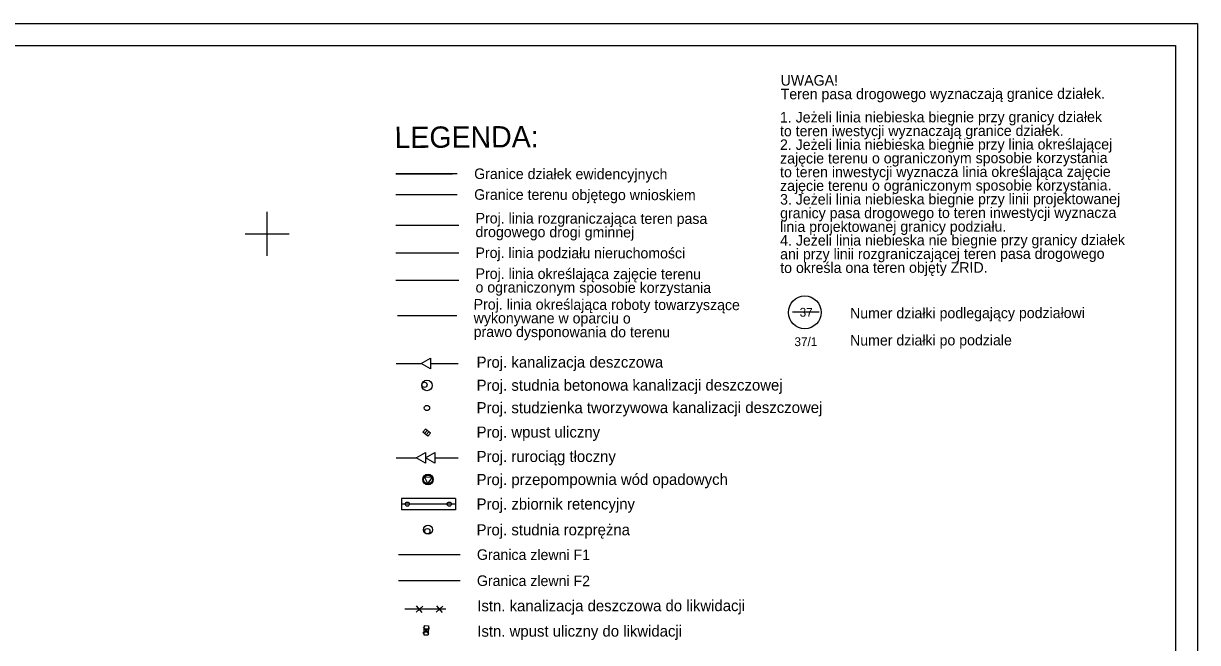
# Model space of a CAD drawing. Extents: x 6512606 to 6513006, y 6022524 to 6022728.
# Drawn here: x 6512872.3 to 6513005.7, y 6022653.6 to 6022723.9 of the extents above; entities that cross this region are included whole.
import ezdxf

# ---------------------------------------------------------------- set-up
doc = ezdxf.new("R2010")
doc.units = 0
for name, color, linetype in [('10', 7, 'Continuous'), ('211-numer działki ewidencyjnej', 7, 'Continuous'), ('3', 7, 'Continuous'), ('4', 7, 'Continuous'), ('6', 7, 'Continuous'), ('Default', 7, 'Continuous'), ('kratka ściekowa (punkt)', 7, 'Continuous'), ('Level 55', 7, 'Continuous'), ('Level 59', 7, 'Continuous'), ('maxp_kan_deszczowa', 7, 'Continuous'), ('maxp_kratki', 7, 'Continuous'), ('maxp_ramka_2', 7, 'Continuous'), ('przewód kanalizacyjny (linia)', 7, 'Continuous')]:
    doc.layers.add(name, color=color, linetype=linetype)

# ---------------------------------------------------------------- blocks, each defined once
blk = doc.blocks.new('US05')
at = {"layer": 'Default'}
for p, q in [((-5.25, -2.5), (-5.25, 2.5)), ((-5.25, 2.5), (-1.75, 2.5)), ((-1.75, -2.5), (-1.75, 2.5)), ((-1.75, 2.5), (1.75, 2.5)), ((1.75, -2.5), (1.75, 2.5)), ((1.75, 2.5), (5.25, 2.5)), ((5.25, -2.5), (5.25, 2.5)), ((-5.25, -2.5), (-1.75, -2.5)), ((-1.75, -2.5), (1.75, -2.5)), ((1.75, -2.5), (5.25, -2.5))]:
    blk.add_line(p, q, dxfattribs=at)

msp = doc.modelspace()

# ---------------------------------------------------------------- linework, layer by layer
at = {"layer": '10'}
for p, q in [((6512914.6, 6022706.82), (6512921.06, 6022706.82)), ((6512914.6, 6022706.82), (6512921.06, 6022706.82)), ((6512914.6, 6022706.82), (6512921.06, 6022706.82)), ((6512921.06, 6022706.82), (6512914.6, 6022706.82)), ((6512921.06, 6022706.82), (6512914.81, 6022706.82)), ((6512921.59, 6022706.82), (6512915.47, 6022706.82)), ((6512914.6, 6022704.46), (6512921.59, 6022704.46)), ((6512914.6, 6022700.99), (6512921.75, 6022700.99)), ((6512914.6, 6022697.85), (6512921.75, 6022697.85)), ((6512914.6, 6022694.71), (6512921.75, 6022694.71))]:
    msp.add_line(p, q, dxfattribs=at)
at = {"layer": '3'}
msp.add_line((6512959.66, 6022691.13), (6512962.7, 6022691.13), dxfattribs=at)
at = {"layer": '6'}
msp.add_circle((6512961.06, 6022691.07), 1.86, dxfattribs=at)
at = {"layer": 'Default'}
for p, q in [((6512900, 6022697.5), (6512900, 6022702.5)), ((6512897.5, 6022700), (6512902.5, 6022700))]:
    msp.add_line(p, q, dxfattribs=at)
at = {"layer": 'Level 55'}
for centre, radius in [((6512917.86, 6022682.84), 0.3), ((6512917.86, 6022682.84), 0.3), ((6512915.92, 6022669.29), 0.24), ((6512920.68, 6022669.29), 0.24), ((6512918.19, 6022666.22), 0.3)]:
    msp.add_circle(centre, radius, dxfattribs=at)
at = {"layer": 'maxp_kan_deszczowa'}
for p, q in [((6512914.65, 6022685.26), (6512917.48, 6022685.26)), ((6512918.53, 6022685.26), (6512921.68, 6022685.26)), ((6512914.65, 6022674.55), (6512916.93, 6022674.55)), ((6512919.03, 6022674.55), (6512921.68, 6022674.55)), ((6512921.38, 6022669.93), (6512915.25, 6022669.93)), ((6512915.25, 6022669.93), (6512915.25, 6022668.65)), ((6512921.38, 6022669.29), (6512915.25, 6022669.29)), ((6512921.38, 6022669.93), (6512921.38, 6022668.65)), ((6512921.38, 6022668.65), (6512915.25, 6022668.65)), ((6512914.91, 6022663.56), (6512921.9, 6022663.56)), ((6512914.91, 6022660.6), (6512921.9, 6022660.6)), ((6512916.91, 6022657.03), (6512917.66, 6022657.69)), ((6512917.61, 6022656.98), (6512916.95, 6022657.73)), ((6512919.2, 6022657.03), (6512919.95, 6022657.69)), ((6512919.91, 6022656.98), (6512919.25, 6022657.73)), ((6512917.67, 6022654.64), (6512918.45, 6022655.27)), ((6512918.37, 6022654.57), (6512917.75, 6022655.35))]:
    msp.add_line(p, q, dxfattribs=at)
for points in [[(6512918.53, 6022684.65), (6512917.48, 6022685.26), (6512918.53, 6022685.86)], [(6512917.98, 6022673.94), (6512916.93, 6022674.55), (6512917.98, 6022675.15)], [(6512919.03, 6022673.94), (6512917.98, 6022674.55), (6512919.03, 6022675.15)], [(6512917.85, 6022672.37), (6512918.23, 6022671.59), (6512918.72, 6022672.32)], [(6512917.85, 6022672.37), (6512918.23, 6022671.59), (6512918.72, 6022672.32)]]:
    msp.add_lwpolyline(points, close=True, dxfattribs=at)
for centre, radius in [((6512918.15, 6022682.77), 0.6), ((6512918.14, 6022680.21), 0.3), ((6512918.27, 6022672.09), 0.6), ((6512918.27, 6022672.09), 0.5), ((6512918.27, 6022666.39), 0.5)]:
    msp.add_circle(centre, radius, dxfattribs=at)
at = {"layer": 'maxp_kratki'}
for p, q in [((6512917.68, 6022677.47), (6512917.97, 6022677.82)), ((6512918.26, 6022677), (6512917.68, 6022677.47)), ((6512917.87, 6022677.32), (6512918.16, 6022677.66)), ((6512918.55, 6022677.34), (6512917.97, 6022677.82)), ((6512918.07, 6022677.16), (6512918.35, 6022677.5)), ((6512918.26, 6022677), (6512918.55, 6022677.34))]:
    msp.add_line(p, q, dxfattribs=at)
at = {"layer": 'maxp_ramka_2'}
msp.add_line((6512914.79, 6022690.71), (6512921.55, 6022690.71), dxfattribs=at)
for points in [[(6512605.66, 6022723.88), (6513005.66, 6022723.88), (6513005.66, 6022523.88), (6512605.66, 6022523.88)], [(6512618.16, 6022526.38), (6512618.16, 6022721.38), (6513003.16, 6022721.38), (6513003.16, 6022526.38)]]:
    msp.add_lwpolyline(points, close=True, dxfattribs=at)
at = {"layer": 'przewód kanalizacyjny (linia)'}
msp.add_lwpolyline([(6512920.28, 6022657.36), (6512915.63, 6022657.36)], dxfattribs=at)

# ---------------------------------------------------------------- block references
at = {"layer": 'kratka ściekowa (punkt)', "xscale": 0.1, "yscale": 0.10000000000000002, "rotation": -91.211}
msp.add_blockref('US05', (6512918.05, 6022654.96), dxfattribs=at)

# ---------------------------------------------------------------- texts
at = {"layer": '10'}
for s, height, rotation, p in [('UWAGA!', 1.2, 0.0917, (6512958.32, 6022716.82)), ('Teren pasa drogowego wyznaczają granice działek.', 1.2, 0.0917, (6512958.32, 6022715.27)), ('1. Jeżeli linia niebieska biegnie przy granicy działek', 1.2, 0.0917, (6512958.24, 6022712.63)), ('LEGENDA:', 2.42, 0.2979, (6512914.47, 6022709.74)), ('to teren iwestycji wyznaczają granice działek.', 1.2, 0.0917, (6512958.24, 6022711.07)), ('2. Jeżeli linia niebieska biegnie przy linia określającej', 1.2, 0.0917, (6512958.24, 6022709.52)), ('zajęcie terenu o ograniczonym sposobie korzystania', 1.2, 0.0917, (6512958.25, 6022707.97)), ('Granice działek ewidencyjnych', 1.2, 359.8681, (6512923.51, 6022706.22)), ('to teren inwestycji wyznacza linia określająca zajęcie ', 1.2, 0.0917, (6512958.25, 6022706.41)), ('zajęcie terenu o ograniczonym sposobie korzystania.', 1.2, 0.0917, (6512958.25, 6022704.86)), ('Granice terenu objętego wnioskiem', 1.2, 359.8681, (6512923.51, 6022703.86)), ('3. Jeżeli linia niebieska biegnie przy linii projektowanej', 1.2, 0.0917, (6512958.25, 6022703.31)), ('granicy pasa drogowego to teren inwestycji wyznacza', 1.2, 0.0917, (6512958.26, 6022701.75)), ('Proj. linia rozgraniczająca teren pasa ', 1.2, 359.8681, (6512923.67, 6022701.17)), ('linia projektowanej granicy podziału.', 1.2, 0.0917, (6512958.26, 6022700.2)), ('drogowego drogi gminnej', 1.2, 359.8681, (6512923.66, 6022699.62)), ('4. Jeżeli linia niebieska nie biegnie przy granicy działek', 1.2, 0.0917, (6512958.26, 6022698.65)), ('Proj. linia podziału nieruchomości', 1.2, 359.8681, (6512923.66, 6022697.25)), ('ani przy linii rozgraniczającej teren pasa drogowego', 1.2, 0.0917, (6512958.26, 6022697.1)), ('Proj. linia określająca zajęcie terenu', 1.2, 359.8681, (6512923.67, 6022694.88)), ('to określa ona teren objęty ZRID.', 1.2, 0.0917, (6512958.27, 6022695.54)), ('o ograniczonym sposobie korzystania', 1.2, 359.8681, (6512923.66, 6022693.33)), ('Numer działki podlegający podziałowi', 1.2, 0.0917, (6512966.2, 6022690.38)), ('Numer działki po podziale', 1.2, 0.0917, (6512966.2, 6022687.3)), ('Granica zlewni F1', 1.2, 359.8681, (6512923.82, 6022662.96)), ('Granica zlewni F2', 1.2, 359.8681, (6512923.82, 6022660))]:
    msp.add_text(s, height=height, rotation=rotation, dxfattribs=at).set_placement(p)
at = {"layer": '211-numer działki ewidencyjnej'}
for s, p in [('37', (6512960.47, 6022690.58)), ('37/1', (6512959.88, 6022687.24))]:
    msp.add_text(s, height=1, dxfattribs=at).set_placement(p)
at = {"layer": '4'}
msp.add_text('37', height=1, dxfattribs=at).set_placement((6512960.47, 6022690.58))
at = {"layer": 'Level 59'}
for s, p in [('Proj. kanalizacja deszczowa', (6512923.78, 6022684.78)), ('Proj. studnia betonowa kanalizacji deszczowej', (6512923.78, 6022682.16)), ('Proj. studzienka tworzywowa kanalizacji deszczowej', (6512923.78, 6022679.61)), ('Proj. wpust uliczny', (6512923.78, 6022676.84)), ('Proj. rurociąg tłoczny ', (6512923.78, 6022674.07)), ('Proj. przepompownia wód opadowych', (6512923.78, 6022671.45)), ('Proj. zbiornik retencyjny', (6512923.78, 6022668.67)), ('Proj. studnia rozprężna', (6512923.78, 6022665.74)), ('Istn. kanalizacja deszczowa do likwidacji', (6512923.86, 6022657.11)), ('Istn. wpust uliczny do likwidacji', (6512923.86, 6022654.23))]:
    msp.add_text(s, height=1.2672, rotation=0.0505, dxfattribs=at).set_placement(p)
at = {"layer": 'maxp_ramka_2'}
for s, p in [('Proj. linia określająca roboty towarzyszące', (6512923.45, 6022691.39)), ('wykonywane w oparciu o ', (6512923.45, 6022689.84)), ('prawo dysponowania do terenu', (6512923.45, 6022688.28))]:
    msp.add_text(s, height=1.2, rotation=359.8681, dxfattribs=at).set_placement(p)

doc.saveas('drawing.dxf')
